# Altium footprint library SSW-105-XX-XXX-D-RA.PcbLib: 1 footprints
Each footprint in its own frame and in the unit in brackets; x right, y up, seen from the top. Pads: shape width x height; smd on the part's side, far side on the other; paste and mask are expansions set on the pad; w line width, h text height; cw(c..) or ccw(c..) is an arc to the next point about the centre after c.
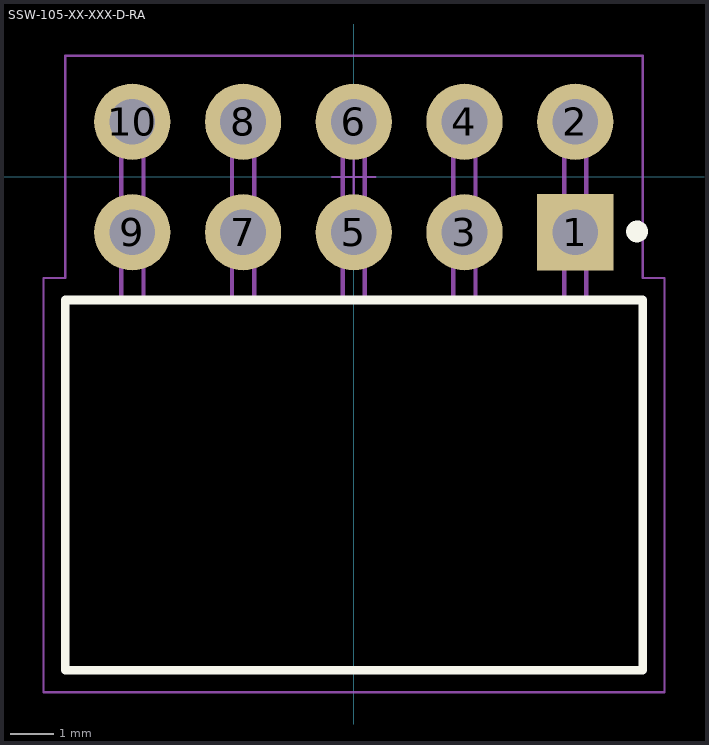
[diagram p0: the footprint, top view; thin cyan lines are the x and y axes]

## SSW-105-XX-XXX-D-RA [mm] "2.54mm pitch, 10 pin, socket strip; r/a, double row"
height 8.51
pads (10):
  rect 1.75x1.75 / inner round 1.75 / far side rect 1.75x1.75 hole 1.05 mask+0: 1(5.08,-1.27)
  round 1.75 hole 1.05 mask+0: 2(5.08,1.27) 3(2.54,-1.27) 4(2.54,1.27) 5(0,-1.27) 6(0,1.27) 7(-2.54,-1.27) 8(-2.54,1.27) 9(-5.08,-1.27) 10(-5.08,1.27)
Top Overlay:
  circle w0.25: c6.5,-1.25 r0.125
  lines w0.2: -6.62,-11.32 -6.62,-2.82 6.63,-2.82 6.63,-11.32 -6.62,-11.32
Mechanical 12:
  lines w0.001: -6.62,-11.32 -6.62,-2.82 6.63,-2.82 6.63,-11.32 -6.62,-11.32
Mechanical 13:
  lines w0.1: -5.334,-2.794 -5.334,1.524 -4.826,1.524 -4.826,-2.794 ; -2.794,-2.794 -2.794,1.524 -2.286,1.524 -2.286,-2.794 ; -0.254,-2.794 -0.254,1.524 0.254,1.524 0.254,-2.794 ; 2.286,-2.794 2.286,1.524 2.794,1.524 2.794,-2.794 ; 4.826,-2.794 4.826,1.524 5.334,1.524 5.334,-2.794 ; -6.62,-11.32 -6.62,-2.82 6.63,-2.82 6.63,-11.32 -6.62,-11.32
  text ".Designator" at 0,-0.127 h1.52
Mechanical 15:
  lines w0.05: -0.5,0 0.5,0 ; 0,-0.5 0,0.5 ; -7.12,-11.82 -7.12,-2.32 -6.62,-2.32 -6.62,2.78 6.63,2.78 6.63,-2.32 7.13,-2.32 7.13,-11.82 -7.12,-11.82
